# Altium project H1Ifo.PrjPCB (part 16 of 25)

## Sheet IfoSqz3B.SchDoc: D1800185
size C; Engineer: Daniel Sigg; DocumentNumber: 7; Revision: 4; SheetNumber: 7; SheetTotal: 10
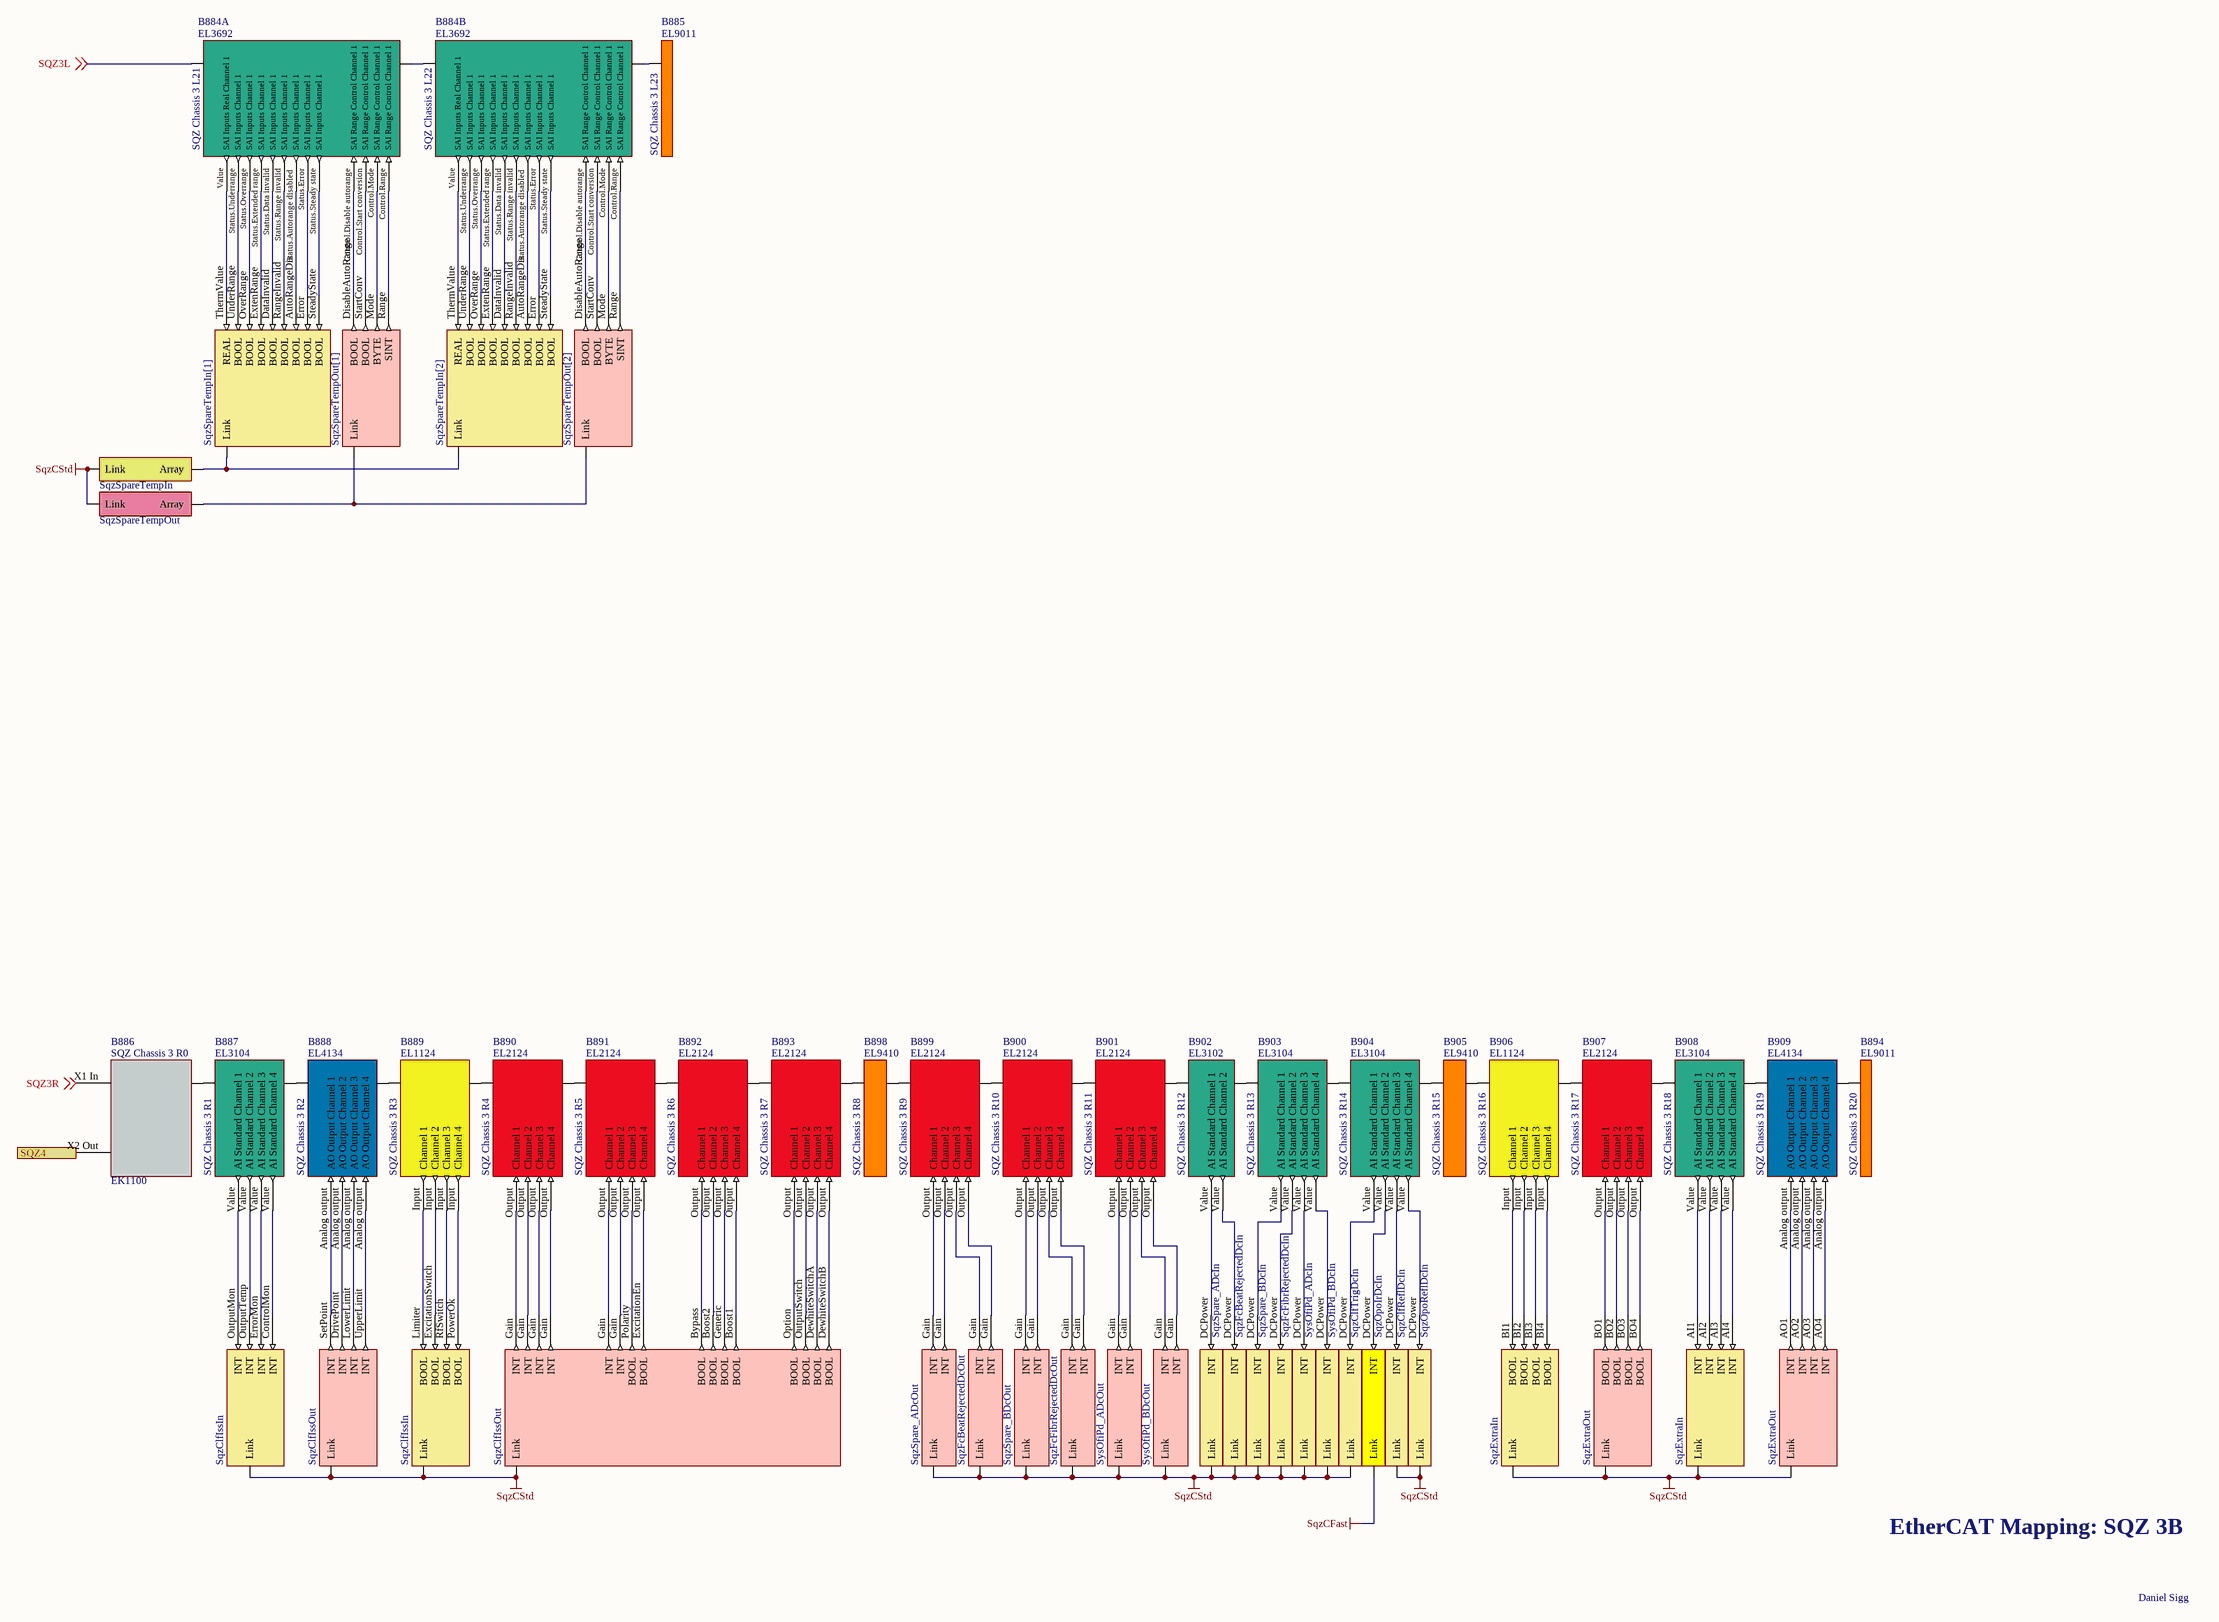
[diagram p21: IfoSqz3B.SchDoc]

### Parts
B884A  SQZ Chassis 3 L21  Part Number: EL3692  (mechanical)
B884B  SQZ Chassis 3 L22  Part Number: EL3692  (mechanical)
B885  SQZ Chassis 3 L23  Part Number: EL9011  (mechanical)
B886  SQZ Chassis 3 R0  Part Number: EK1100
B887  SQZ Chassis 3 R1  Part Number: EL3104  (mechanical)
B888  SQZ Chassis 3 R2  Part Number: EL4134  (mechanical)
B889  SQZ Chassis 3 R3  Part Number: EL1124  (mechanical)
B890  SQZ Chassis 3 R4  Part Number: EL2124  (mechanical)
B891  SQZ Chassis 3 R5  Part Number: EL2124  (mechanical)
B892  SQZ Chassis 3 R6  Part Number: EL2124  (mechanical)
B893  SQZ Chassis 3 R7  Part Number: EL2124  (mechanical)
B894  SQZ Chassis 3 R20  Part Number: EL9011  (mechanical)
B898  SQZ Chassis 3 R8  Part Number: EL9410  (mechanical)
B899  SQZ Chassis 3 R9  Part Number: EL2124  (mechanical)
B900  SQZ Chassis 3 R10  Part Number: EL2124  (mechanical)
B901  SQZ Chassis 3 R11  Part Number: EL2124  (mechanical)
B902  SQZ Chassis 3 R12  Part Number: EL3102  (mechanical)
B903  SQZ Chassis 3 R13  Part Number: EL3104  (mechanical)
B904  SQZ Chassis 3 R14  Part Number: EL3104  (mechanical)
B905  SQZ Chassis 3 R15  Part Number: EL9410  (mechanical)
B906  SQZ Chassis 3 R16  Part Number: EL1124  (mechanical)
B907  SQZ Chassis 3 R17  Part Number: EL2124  (mechanical)
B908  SQZ Chassis 3 R18  Part Number: EL3104  (mechanical)
B909  SQZ Chassis 3 R19  Part Number: EL4134  (mechanical)
V410  SqzClfIssIn  (parts A,B of 2)  (no BOM)
V411  SqzClfIssOut  (parts A,B of 2)  (no BOM)
V701  SqzSpareTempIn[1]  (no BOM)
V702  SqzSpareTempOut[1]  (no BOM)
V703  SqzSpareTempIn[2]  (no BOM)
V704  SqzSpareTempOut[2]  (no BOM)
V705  SqzSpareTempIn  (no BOM)
V706  SqzSpareTempOut  (no BOM)
V722  SqzSpare_ADcOut  (no BOM)
V723  SqzFcBeatRejectedDcOut  (no BOM)
V724  SqzFcFibrRejectedDcOut  (no BOM)
V725  SqzSpare_BDcOut  (no BOM)
V726  SysOfiPd_ADcOut  (no BOM)
V727  SysOfiPd_BDcOut  (no BOM)
V728  SqzSpare_ADcIn  (no BOM)
V729  SqzFcBeatRejectedDcIn  (no BOM)
V730  SqzFcFibrRejectedDcIn  (no BOM)
V731  SqzSpare_BDcIn  (no BOM)
V732  SysOfiPd_ADcIn  (no BOM)
V733  SysOfiPd_BDcIn  (no BOM)
V734  SqzClfTrigDcIn  (no BOM)
V735  SqzOpoIrDcIn  (no BOM)
V736  SqzClfReflDcIn  (no BOM)
V737  SqzOpoReflDcIn  (no BOM)
V738  SqzExtraIn  (parts A,B of 2)  (no BOM)
V739  SqzExtraOut  (parts A,B of 2)  (no BOM)

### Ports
SQZ4

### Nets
SqzCFast: V735.1(Link)
SqzCStd: V410.0(Link) V410.1(Link) V411.0(Link) V411.1(Link) V705.?1(Link) V706.?1(Link) V722.0(Link) V723.0(Link) V724.0(Link) V725.0(Link) V726.0(Link) V727.0(Link) V728.1(Link) V729.1(Link) V730.1(Link) V731.1(Link) V732.1(Link) V733.1(Link) V734.1(Link) V736.1(Link) V737.1(Link) V738.0(Link) V738.1(Link) V739.0(Link) V739.1(Link)
SQZ3L: B884A.Ebus(A) ; off-sheet SQZ3L
SQZ3R: B886.X1_In(A) ; off-sheet SQZ3R
NetB884A_Control.Disable autorange: B884A.Control.Disable_autorange(SAI_Range_Control_Channel_1) V702.DisableAutoRange(BOOL)
NetB884A_Control.Mode: B884A.Control.Mode(SAI_Range_Control_Channel_1) V702.Mode(BYTE)
NetB884A_Control.Range: B884A.Control.Range(SAI_Range_Control_Channel_1) V702.Range(SINT)
NetB884A_Control.Start conversion: B884A.Control.Start_conversion(SAI_Range_Control_Channel_1) V702.StartConv(BOOL)
NetB884A_Ebus: B884A.Ebus(B) B884B.Ebus(A)
NetB884A_Status.Autorange disabled: B884A.Status.Autorange_disabled(SAI_Inputs_Channel_1) V701.AutoRangeDis(BOOL)
NetB884A_Status.Data invalid: B884A.Status.Data_invalid(SAI_Inputs_Channel_1) V701.DataInvalid(BOOL)
NetB884A_Status.Error: B884A.Status.Error(SAI_Inputs_Channel_1) V701.Error(BOOL)
NetB884A_Status.Extended range: B884A.Status.Extended_range(SAI_Inputs_Channel_1) V701.ExtenRange(BOOL)
NetB884A_Status.Overrange: B884A.Status.Overrange(SAI_Inputs_Channel_1) V701.OverRange(BOOL)
NetB884A_Status.Range invalid: B884A.Status.Range_invalid(SAI_Inputs_Channel_1) V701.RangeInvalid(BOOL)
NetB884A_Status.Steady state: B884A.Status.Steady_state(SAI_Inputs_Channel_1) V701.SteadyState(BOOL)
NetB884A_Status.Underrange: B884A.Status.Underrange(SAI_Inputs_Channel_1) V701.UnderRange(BOOL)
NetB884A_Value: B884A.Value(SAI_Inputs_Real_Channel_1) V701.ThermValue(REAL)
NetB884B_Control.Disable autorange: B884B.Control.Disable_autorange(SAI_Range_Control_Channel_1) V704.DisableAutoRange(BOOL)
NetB884B_Control.Mode: B884B.Control.Mode(SAI_Range_Control_Channel_1) V704.Mode(BYTE)
NetB884B_Control.Range: B884B.Control.Range(SAI_Range_Control_Channel_1) V704.Range(SINT)
NetB884B_Control.Start conversion: B884B.Control.Start_conversion(SAI_Range_Control_Channel_1) V704.StartConv(BOOL)
NetB884B_Ebus: B884B.Ebus(B) B885.Ebus(A)
NetB884B_Status.Autorange disabled: B884B.Status.Autorange_disabled(SAI_Inputs_Channel_1) V703.AutoRangeDis(BOOL)
NetB884B_Status.Data invalid: B884B.Status.Data_invalid(SAI_Inputs_Channel_1) V703.DataInvalid(BOOL)
NetB884B_Status.Error: B884B.Status.Error(SAI_Inputs_Channel_1) V703.Error(BOOL)
NetB884B_Status.Extended range: B884B.Status.Extended_range(SAI_Inputs_Channel_1) V703.ExtenRange(BOOL)
NetB884B_Status.Overrange: B884B.Status.Overrange(SAI_Inputs_Channel_1) V703.OverRange(BOOL)
NetB884B_Status.Range invalid: B884B.Status.Range_invalid(SAI_Inputs_Channel_1) V703.RangeInvalid(BOOL)
NetB884B_Status.Steady state: B884B.Status.Steady_state(SAI_Inputs_Channel_1) V703.SteadyState(BOOL)
NetB884B_Status.Underrange: B884B.Status.Underrange(SAI_Inputs_Channel_1) V703.UnderRange(BOOL)
NetB884B_Value: B884B.Value(SAI_Inputs_Real_Channel_1) V703.ThermValue(REAL)
NetB886_Ebus: B886.Ebus(B) B887.Ebus(A)
NetB886_X2 Out: B886.X2_Out(C) ; port SQZ4
NetB887_Ebus: B887.Ebus(B) B888.Ebus(A)
NetB887_Value: B887.Value(AI_Standard_Channel_1) V410.OutputMon(INT)
NetB887_Value: B887.Value(AI_Standard_Channel_2) V410.OutputTemp(INT)  [a separate net that carries the same name]
NetB887_Value: B887.Value(AI_Standard_Channel_3) V410.ErrorMon(INT)  [a separate net that carries the same name]
NetB887_Value: B887.Value(AI_Standard_Channel_4) V410.ControlMon(INT)  [a separate net that carries the same name]
NetB888_Analog output: B888.Analog_output(AO_Output_Channel_1) V411.SetPoint(INT)
NetB888_Analog output: B888.Analog_output(AO_Output_Channel_2) V411.DrivePoint(INT)  [a separate net that carries the same name]
NetB888_Analog output: B888.Analog_output(AO_Output_Channel_3) V411.LowerLimit(INT)  [a separate net that carries the same name]
NetB888_Analog output: B888.Analog_output(AO_Output_Channel_4) V411.UpperLimit(INT)  [a separate net that carries the same name]
NetB888_Ebus: B888.Ebus(B) B889.Ebus(A)
NetB889_Ebus: B889.Ebus(B) B890.Ebus(A)
NetB889_Input: B889.Input(Channel_1) V410.Limiter(BOOL)
NetB889_Input: B889.Input(Channel_2) V410.ExcitationSwitch(BOOL)  [a separate net that carries the same name]
NetB889_Input: B889.Input(Channel_3) V410.RfSwitch(BOOL)  [a separate net that carries the same name]
NetB889_Input: B889.Input(Channel_4) V410.PowerOk(BOOL)  [a separate net that carries the same name]
NetB890_Ebus: B890.Ebus(B) B891.Ebus(A)
NetB890_Output: B890.Output(Channel_1) V411.Gain(INT)
NetB890_Output: B890.Output(Channel_2) V411.Gain(INT)  [a separate net that carries the same name]
NetB890_Output: B890.Output(Channel_3) V411.Gain(INT)  [a separate net that carries the same name]
NetB890_Output: B890.Output(Channel_4) V411.Gain(INT)  [a separate net that carries the same name]
NetB891_Ebus: B891.Ebus(B) B892.Ebus(A)
NetB891_Output: B891.Output(Channel_1) V411.Gain(INT)
NetB891_Output: B891.Output(Channel_2) V411.Gain(INT)  [a separate net that carries the same name]
NetB891_Output: B891.Output(Channel_3) V411.Polarity(BOOL)  [a separate net that carries the same name]
NetB891_Output: B891.Output(Channel_4) V411.ExcitationEn(BOOL)  [a separate net that carries the same name]
NetB892_Ebus: B892.Ebus(B) B893.Ebus(A)
NetB892_Output: B892.Output(Channel_1) V411.Bypass(BOOL)
NetB892_Output: B892.Output(Channel_2) V411.Boost2(BOOL)  [a separate net that carries the same name]
NetB892_Output: B892.Output(Channel_3) V411.Generic(BOOL)  [a separate net that carries the same name]
NetB892_Output: B892.Output(Channel_4) V411.Boost1(BOOL)  [a separate net that carries the same name]
NetB893_Ebus: B893.Ebus(B) B898.Ebus(A)
NetB893_Output: B893.Output(Channel_1) V411.Option(BOOL)
NetB893_Output: B893.Output(Channel_2) V411.OutputSwitch(BOOL)  [a separate net that carries the same name]
NetB893_Output: B893.Output(Channel_3) V411.DewhiteSwitchA(BOOL)  [a separate net that carries the same name]
NetB893_Output: B893.Output(Channel_4) V411.DewhiteSwitchB(BOOL)  [a separate net that carries the same name]
NetB894_Ebus: B894.Ebus(A) B909.Ebus(B)
NetB898_Ebus: B898.Ebus(B) B899.Ebus(A)
NetB899_Ebus: B899.Ebus(B) B900.Ebus(A)
NetB899_Output: B899.Output(Channel_1) V722.Gain(INT)
NetB899_Output: B899.Output(Channel_2) V722.Gain(INT)  [a separate net that carries the same name]
NetB899_Output: B899.Output(Channel_3) V723.Gain(INT)  [a separate net that carries the same name]
NetB899_Output: B899.Output(Channel_4) V723.Gain(INT)  [a separate net that carries the same name]
NetB900_Ebus: B900.Ebus(B) B901.Ebus(A)
NetB900_Output: B900.Output(Channel_1) V725.Gain(INT)
NetB900_Output: B900.Output(Channel_2) V725.Gain(INT)  [a separate net that carries the same name]
NetB900_Output: B900.Output(Channel_3) V724.Gain(INT)  [a separate net that carries the same name]
NetB900_Output: B900.Output(Channel_4) V724.Gain(INT)  [a separate net that carries the same name]
NetB901_Ebus: B901.Ebus(B) B902.Ebus(A)
NetB901_Output: B901.Output(Channel_1) V726.Gain(INT)
NetB901_Output: B901.Output(Channel_2) V726.Gain(INT)  [a separate net that carries the same name]
NetB901_Output: B901.Output(Channel_3) V727.Gain(INT)  [a separate net that carries the same name]
NetB901_Output: B901.Output(Channel_4) V727.Gain(INT)  [a separate net that carries the same name]
NetB902_Ebus: B902.Ebus(B) B903.Ebus(A)
NetB902_Value: B902.Value(AI_Standard_Channel_1) V728.DCPower(INT)
NetB902_Value: B902.Value(AI_Standard_Channel_2) V729.DCPower(INT)  [a separate net that carries the same name]
NetB903_Ebus: B903.Ebus(B) B904.Ebus(A)
NetB903_Value: B903.Value(AI_Standard_Channel_1) V731.DCPower(INT)
NetB903_Value: B903.Value(AI_Standard_Channel_2) V730.DCPower(INT)  [a separate net that carries the same name]
NetB903_Value: B903.Value(AI_Standard_Channel_3) V732.DCPower(INT)  [a separate net that carries the same name]
NetB903_Value: B903.Value(AI_Standard_Channel_4) V733.DCPower(INT)  [a separate net that carries the same name]
NetB904_Ebus: B904.Ebus(B) B905.Ebus(A)
NetB904_Value: B904.Value(AI_Standard_Channel_1) V734.DCPower(INT)
NetB904_Value: B904.Value(AI_Standard_Channel_2) V735.DCPower(INT)  [a separate net that carries the same name]
NetB904_Value: B904.Value(AI_Standard_Channel_3) V736.DCPower(INT)  [a separate net that carries the same name]
NetB904_Value: B904.Value(AI_Standard_Channel_4) V737.DCPower(INT)  [a separate net that carries the same name]
NetB905_Ebus: B905.Ebus(B) B906.Ebus(A)
NetB906_Ebus: B906.Ebus(B) B907.Ebus(A)
NetB906_Input: B906.Input(Channel_1) V738.BI1(BOOL)
NetB906_Input: B906.Input(Channel_2) V738.BI2(BOOL)  [a separate net that carries the same name]
NetB906_Input: B906.Input(Channel_3) V738.BI3(BOOL)  [a separate net that carries the same name]
NetB906_Input: B906.Input(Channel_4) V738.BI4(BOOL)  [a separate net that carries the same name]
NetB907_Ebus: B907.Ebus(B) B908.Ebus(A)
NetB907_Output: B907.Output(Channel_1) V739.BO1(BOOL)
NetB907_Output: B907.Output(Channel_2) V739.BO2(BOOL)  [a separate net that carries the same name]
NetB907_Output: B907.Output(Channel_3) V739.BO3(BOOL)  [a separate net that carries the same name]
NetB907_Output: B907.Output(Channel_4) V739.BO4(BOOL)  [a separate net that carries the same name]
NetB908_Ebus: B908.Ebus(B) B909.Ebus(A)
NetB908_Value: B908.Value(AI_Standard_Channel_1) V738.AI1(INT)
NetB908_Value: B908.Value(AI_Standard_Channel_2) V738.AI2(INT)  [a separate net that carries the same name]
NetB908_Value: B908.Value(AI_Standard_Channel_3) V738.AI3(INT)  [a separate net that carries the same name]
NetB908_Value: B908.Value(AI_Standard_Channel_4) V738.AI4(INT)  [a separate net that carries the same name]
NetB909_Analog output: B909.Analog_output(AO_Output_Channel_1) V739.AO1(INT)
NetB909_Analog output: B909.Analog_output(AO_Output_Channel_2) V739.AO2(INT)  [a separate net that carries the same name]
NetB909_Analog output: B909.Analog_output(AO_Output_Channel_3) V739.AO3(INT)  [a separate net that carries the same name]
NetB909_Analog output: B909.Analog_output(AO_Output_Channel_4) V739.AO4(INT)  [a separate net that carries the same name]
NetV701_1: V701.1(Link) V703.1(Link) V705.?2(Array)
NetV702_1: V702.1(Link) V704.1(Link) V706.?2(Array)

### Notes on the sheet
- EtherCAT Mapping: SQZ 3B
- Daniel Sigg

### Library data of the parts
B884A = TerminalEL3692-1chn: EtherCAT Terminal EL3692 1-chn Resistance Measurement; Rail: Left; BoxNextB: HCCQCWHL; BoxPrev: FHTRRYRM; PortPrevFull: 1141/B; PortPrevShort: B; Fullname: TIID^Vertex Squeezer (EtherCAT)^SQZ Chassis 3 L0 (EK1101)^SQZ Chassis 3 L21 (EL3692); BoxAddr: 1142; PDO Inputs: 0x1A00,0x1A02; PDO Outputs: 0x1600; Disabled: False
B884B = TerminalEL3692-1chn: EtherCAT Terminal EL3692 1-chn Resistance Measurement; Rail: Left; BoxNextB: CYSUGKJU; BoxPrev: BXXLOSJW; PortPrevFull: 1142/B; PortPrevShort: B; Fullname: TIID^Vertex Squeezer (EtherCAT)^SQZ Chassis 3 L0 (EK1101)^SQZ Chassis 3 L22 (EL3692); BoxAddr: 1143; PDO Inputs: 0x1A00,0x1A02; PDO Outputs: 0x1600; Disabled: False
B885 = TerminalEL9011: EtherCAT Terminal EL9011 End; BoxType: TerminalPassive; Rail: Left; BoxPrev: HCCQCWHL; PortPrevShort: B; Fullname: TIID^Vertex Squeezer (EtherCAT)^SQZ Chassis 3 L0 (EK1101)^SQZ Chassis 3 L23 (EL9011); Disabled: False
B886 = CouplerEK1100: EtherCAT Coupler; Rail: Right; BoxNextB: LMNHRKFK; BoxNextC: BCNOLNHC; BoxPrev: VQWTFMVH; PortPrevFull: 1144/C; PortPrevShort: C 'X2 Out'; Fullname: TIID^Vertex Squeezer (EtherCAT)^SQZ Chassis 3 R0 (EK1100); BoxPorts: Junction; BoxAddr: 1168; Disabled: False
B887 = TerminalEL3104: EtherCAT Terminal EL3104 4-chn Analog Input; Rail: Right; BoxNextB: SAJIWMHJ; BoxPrev: BKUDMEPV; PortPrevFull: 1168/B; PortPrevShort: B; Fullname: TIID^Vertex Squeezer (EtherCAT)^SQZ Chassis 3 R0 (EK1100)^SQZ Chassis 3 R1 (EL3104); BoxAddr: 1169; Disabled: False
B888 = TerminalEL4134: EtherCAT Terminal EL4134 4-chn Analog Ouput; Rail: Right; BoxNextB: JGBHBNGR; BoxPrev: LMNHRKFK; PortPrevFull: 1169/B; PortPrevShort: B; Fullname: TIID^Vertex Squeezer (EtherCAT)^SQZ Chassis 3 R0 (EK1100)^SQZ Chassis 3 R2 (EL4134); BoxAddr: 1170; Disabled: False
B889 = TerminalEL1124: EtherCAT Terminal EL1124 4-chn Digital Input; Rail: Right; BoxNextB: VKBNNKDD; BoxPrev: SAJIWMHJ; PortPrevFull: 1170/B; PortPrevShort: B; Fullname: TIID^Vertex Squeezer (EtherCAT)^SQZ Chassis 3 R0 (EK1100)^SQZ Chassis 3 R3 (EL1124); BoxAddr: 1171; Disabled: False
B890 = TerminalEL2124: EtherCAT Terminal EL2124 4-chn Digital Ouput; Rail: Right; BoxNextB: CQYTOJCV; BoxPrev: JGBHBNGR; PortPrevFull: 1171/B; PortPrevShort: B; Fullname: TIID^Vertex Squeezer (EtherCAT)^SQZ Chassis 3 R0 (EK1100)^SQZ Chassis 3 R4 (EL2124); BoxAddr: 1172; Disabled: False
B891 = TerminalEL2124: EtherCAT Terminal EL2124 4-chn Digital Ouput; Rail: Right; BoxNextB: GUINYQMW; BoxPrev: VKBNNKDD; PortPrevFull: 1172/B; PortPrevShort: B; Fullname: TIID^Vertex Squeezer (EtherCAT)^SQZ Chassis 3 R0 (EK1100)^SQZ Chassis 3 R5 (EL2124); BoxAddr: 1173; Disabled: False
B892 = TerminalEL2124: EtherCAT Terminal EL2124 4-chn Digital Ouput; Rail: Right; BoxNextB: HMWVQJTD; BoxPrev: CQYTOJCV; PortPrevFull: 1173/B; PortPrevShort: B; Fullname: TIID^Vertex Squeezer (EtherCAT)^SQZ Chassis 3 R0 (EK1100)^SQZ Chassis 3 R6 (EL2124); BoxAddr: 1174; Disabled: False
B893 = TerminalEL2124: EtherCAT Terminal EL2124 4-chn Digital Ouput; Rail: Right; BoxNextB: EWXBFFSC; BoxPrev: GUINYQMW; PortPrevFull: 1174/B; PortPrevShort: B; Fullname: TIID^Vertex Squeezer (EtherCAT)^SQZ Chassis 3 R0 (EK1100)^SQZ Chassis 3 R7 (EL2124); BoxAddr: 1175; Disabled: False
B894 = TerminalEL9011: EtherCAT Terminal EL9011 End; BoxType: TerminalPassive; Rail: Right; BoxPrev: REDTJCGQ; PortPrevShort: B; Fullname: TIID^Vertex Squeezer (EtherCAT)^SQZ Chassis 3 R0 (EK1100)^SQZ Chassis 3 R20 (EL9011); Disabled: False
B898 = TerminalEL9410: EtherCAT Terminal EL9410 Power; Rail: Right; BoxNextB: TDWNLRLC; BoxPrev: HMWVQJTD; PortPrevFull: 1175/B; PortPrevShort: B; Fullname: TIID^Vertex Squeezer (EtherCAT)^SQZ Chassis 3 R0 (EK1100)^SQZ Chassis 3 R8 (EL9410); BoxAddr: 1176; Disabled: False
B899 = TerminalEL2124: EtherCAT Terminal EL2124 4-chn Digital Ouput; Rail: Right; BoxNextB: JKJTFGCV; BoxPrev: EWXBFFSC; PortPrevFull: 1176/B; PortPrevShort: B; Fullname: TIID^Vertex Squeezer (EtherCAT)^SQZ Chassis 3 R0 (EK1100)^SQZ Chassis 3 R9 (EL2124); BoxAddr: 1177; Disabled: False
B900 = TerminalEL2124: EtherCAT Terminal EL2124 4-chn Digital Ouput; Rail: Right; BoxNextB: YYBAPAKS; BoxPrev: TDWNLRLC; PortPrevFull: 1177/B; PortPrevShort: B; Fullname: TIID^Vertex Squeezer (EtherCAT)^SQZ Chassis 3 R0 (EK1100)^SQZ Chassis 3 R10 (EL2124); BoxAddr: 1178; Disabled: False
B901 = TerminalEL2124: EtherCAT Terminal EL2124 4-chn Digital Ouput; Rail: Right; BoxNextB: KULEGXXY; BoxPrev: JKJTFGCV; PortPrevFull: 1178/B; PortPrevShort: B; Fullname: TIID^Vertex Squeezer (EtherCAT)^SQZ Chassis 3 R0 (EK1100)^SQZ Chassis 3 R11 (EL2124); BoxAddr: 1179; Disabled: False
B902 = TerminalEL3102: EtherCAT Terminal EL3102 2-chn Analog Input; Rail: Right; BoxNextB: QOIJDIEC; BoxPrev: YYBAPAKS; PortPrevFull: 1179/B; PortPrevShort: B; Fullname: TIID^Vertex Squeezer (EtherCAT)^SQZ Chassis 3 R0 (EK1100)^SQZ Chassis 3 R12 (EL3102); BoxAddr: 1180; Disabled: False
B903 = TerminalEL3104: EtherCAT Terminal EL3104 4-chn Analog Input; Rail: Right; BoxNextB: XSWHLOWF; BoxPrev: KULEGXXY; PortPrevFull: 1180/B; PortPrevShort: B; Fullname: TIID^Vertex Squeezer (EtherCAT)^SQZ Chassis 3 R0 (EK1100)^SQZ Chassis 3 R13 (EL3104); BoxAddr: 1181; Disabled: False
B904 = TerminalEL3104: EtherCAT Terminal EL3104 4-chn Analog Input; Rail: Right; BoxNextB: DXXDEXAW; BoxPrev: QOIJDIEC; PortPrevFull: 1181/B; PortPrevShort: B; Fullname: TIID^Vertex Squeezer (EtherCAT)^SQZ Chassis 3 R0 (EK1100)^SQZ Chassis 3 R14 (EL3104); BoxAddr: 1182; Disabled: False
B905 = TerminalEL9410: EtherCAT Terminal EL9410 Power; Rail: Right; BoxNextB: LQYWWYRA; BoxPrev: XSWHLOWF; PortPrevFull: 1182/B; PortPrevShort: B; Fullname: TIID^Vertex Squeezer (EtherCAT)^SQZ Chassis 3 R0 (EK1100)^SQZ Chassis 3 R15 (EL9410); BoxAddr: 1183; Disabled: False
B906 = TerminalEL1124: EtherCAT Terminal EL1124 4-chn Digital Input; Rail: Right; BoxNextB: KAAFGPDB; BoxPrev: DXXDEXAW; PortPrevFull: 1183/B; PortPrevShort: B; Fullname: TIID^Vertex Squeezer (EtherCAT)^SQZ Chassis 3 R0 (EK1100)^SQZ Chassis 3 R16 (EL1124); BoxAddr: 1184; Disabled: False
B907 = TerminalEL2124: EtherCAT Terminal EL2124 4-chn Digital Ouput; Rail: Right; BoxNextB: YRGWWXTI; BoxPrev: LQYWWYRA; PortPrevFull: 1184/B; PortPrevShort: B; Fullname: TIID^Vertex Squeezer (EtherCAT)^SQZ Chassis 3 R0 (EK1100)^SQZ Chassis 3 R17 (EL2124); BoxAddr: 1185; Disabled: False
B908 = TerminalEL3104: EtherCAT Terminal EL3104 4-chn Analog Input; Rail: Right; BoxNextB: REDTJCGQ; BoxPrev: KAAFGPDB; PortPrevFull: 1185/B; PortPrevShort: B; Fullname: TIID^Vertex Squeezer (EtherCAT)^SQZ Chassis 3 R0 (EK1100)^SQZ Chassis 3 R18 (EL3104); BoxAddr: 1186; Disabled: False
B909 = TerminalEL4134: EtherCAT Terminal EL4134 4-chn Analog Ouput; Rail: Right; BoxNextB: RXFIDCPJ; BoxPrev: YRGWWXTI; PortPrevFull: 1186/B; PortPrevShort: B; Fullname: TIID^Vertex Squeezer (EtherCAT)^SQZ Chassis 3 R0 (EK1100)^SQZ Chassis 3 R19 (EL4134); BoxAddr: 1187; Disabled: False
V410 = Iss_AomServoInStruct: AomServoInStruct; BoxType: Variable; Instance: H1SqzCorner Instance; PLC: H1SqzCorner; Task: SqzCStd
V411 = Iss_AomServoOutStruct: AomServoOutStruct; BoxType: Variable; Instance: H1SqzCorner Instance; PLC: H1SqzCorner; Task: SqzCStd
V701 V703 = TECController_ThermistorInStruct: ThermistorInStruct; BoxType: Variable; Instance: H1SqzCorner Instance; PLC: H1SqzCorner; Task: SqzCStd
V702 V704 = TECController_ThermistorOutStruct: ThermistorOutStruct; BoxType: Variable; Instance: H1SqzCorner Instance; PLC: H1SqzCorner; Task: SqzCStd
V705 = ArrayAggregatorIn: Array [1..2] Of ThermistorInStruct; Instance: H1SqzCorner Instance; PLC: H1SqzCorner; Task: SqzCStd; Lower Bound: 1; Upper Bound: 2
V706 = ArrayAggregatorOut: Array [1..2] Of ThermistorOutStruct; Instance: H1SqzCorner Instance; PLC: H1SqzCorner; Task: SqzCStd; Lower Bound: 1; Upper Bound: 2
V722-V727 = DCPower_DCPowerOutStruct: DCPowerOutStruct; BoxType: Variable; Instance: H1SqzCorner Instance; PLC: H1SqzCorner; Task: SqzCStd
V728-V734 V736 V737 = DCPower_DCPowerInStruct: DCPowerInStruct; BoxType: Variable; Instance: H1SqzCorner Instance; PLC: H1SqzCorner; Task: SqzCStd
V735 = DCPower_DCPowerFastInStruct: DCPowerInStruct; BoxType: Variable; Instance: H1SqzCorner Instance; PLC: H1SqzCorner; Task: SqzCFast
V738 = Auxiliary_AuxiliaryInStruct: AuxiliaryInStruct; BoxType: Variable; Instance: H1SqzCorner Instance; PLC: H1SqzCorner; Task: SqzCStd
V739 = Auxiliary_AuxiliaryOutStruct: AuxiliaryOutStruct; BoxType: Variable; Instance: H1SqzCorner Instance; PLC: H1SqzCorner; Task: SqzCStd

## Sheet IfoEndX0.SchDoc: D1800185
size C; Engineer: Daniel Sigg; DocumentNumber: 4; Revision: 4; SheetNumber: 4; SheetTotal: 8
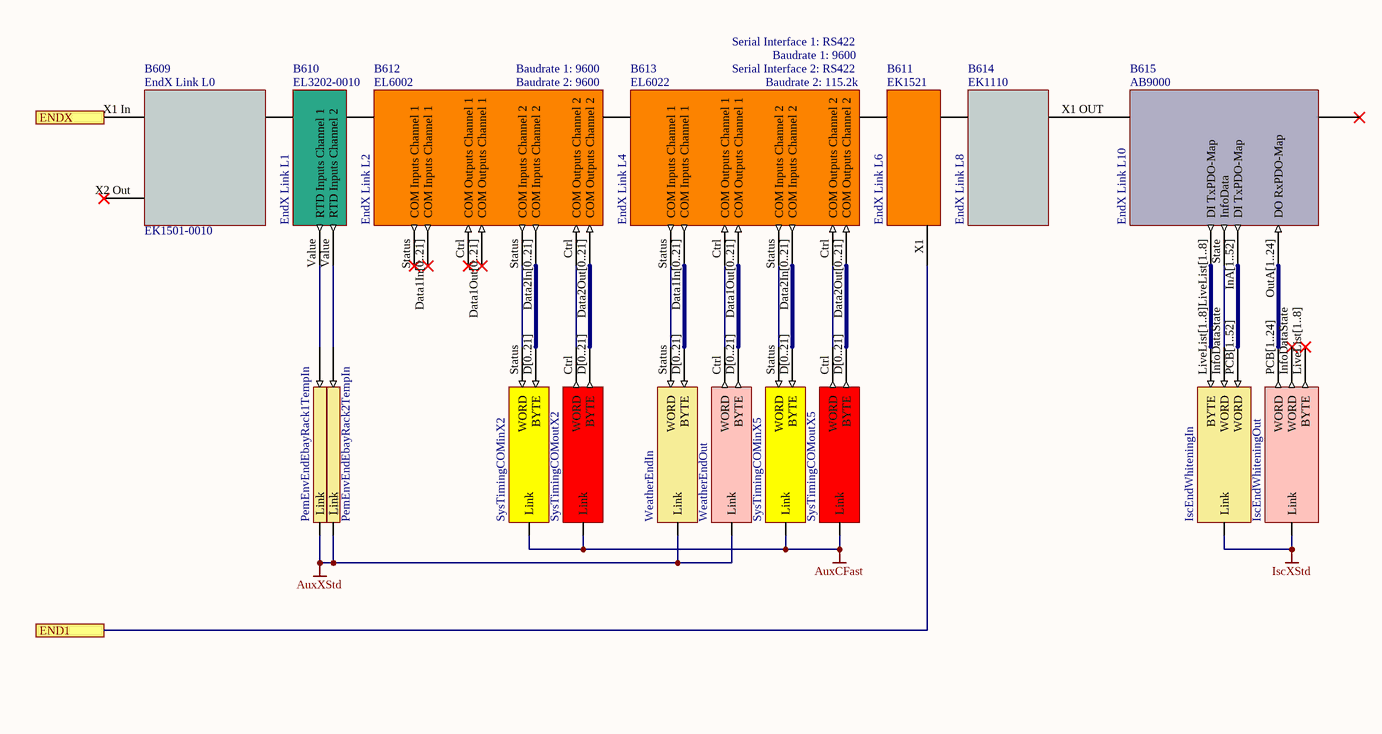
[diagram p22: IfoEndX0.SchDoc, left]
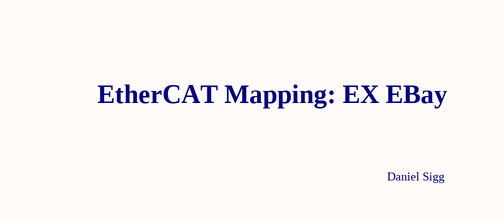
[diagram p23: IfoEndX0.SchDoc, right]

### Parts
B609  EndX Link L0  Part Number: EK1501-0010  (mechanical)
B610  EndX Link L1  Part Number: EL3202-0010  (mechanical)
B611  EndX Link L6  Part Number: EK1521  (mechanical)
B612  EndX Link L2  Part Number: EL6002  Baudrate 1: 9600  (mechanical)
B613  EndX Link L4  Part Number: EL6022  Baudrate 1: 9600  Baudrate 2: 115.2k  Serial Interface 1: RS422  (mechanical)
B614  EndX Link L8  Part Number: EK1110  (mechanical)
B615  EndX Link L10  Part Number: AB9000  (mechanical)
V526  PemEnvEndEbayRack1TempIn  (no BOM)
V527  PemEnvEndEbayRack2TempIn  (no BOM)
V528  IscEndWhiteningIn  (no BOM)
V529  IscEndWhiteningOut  (no BOM)
V530  SysTimingCOMinX2  (no BOM)
V531  SysTimingCOMoutX2  (no BOM)
V533  SysTimingCOMinX5  (no BOM)
V534  SysTimingCOMoutX5  (no BOM)
V845  WeatherEndIn  (no BOM)
V846  WeatherEndOut  (no BOM)

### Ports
END1, ENDX

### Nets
AuxCFast: V530.?1(Link) V531.?1(Link) V533.?1(Link) V534.?1(Link)
AuxXStd: V526.?2(Link) V527.?2(Link) V845.?1(Link) V846.?1(Link)
IscXStd: V528.?1(Link) V529.?1(Link)
NetB609_Ebus: B609.Ebus(B) B610.Ebus(A)
NetB609_X1 In: B609.X1_In(A) ; port ENDX
NetB610_Ebus: B610.Ebus(B) B612.Ebus(A)
NetB610_Value: B610.Value(RTD_Inputs_Channel_1) V526.?1
NetB610_Value: B610.Value(RTD_Inputs_Channel_2) V527.?1  [a separate net that carries the same name]
NetB611_Ebus: B611.Ebus(A) B613.Ebus(B)
NetB611_Ebus: B611.Ebus(C) B614.Ebus(A)  [a separate net that carries the same name]
NetB611_X1: B611.X1(D) ; port END1
NetB612_Ctrl: B612.Ctrl(COM_Outputs_Channel_1) V531.Ctrl(WORD)
NetB612_Data2In[0..21]: B612.Data2In[0..21](COM_Inputs_Channel_2) V530.D[0..21](BYTE)
NetB612_Data2Out[0..21]: B612.Data2Out[0..21](COM_Outputs_Channel_2) V531.D[0..21](BYTE)
NetB612_Ebus: B612.Ebus(B) B613.Ebus(A)
NetB612_Status: B612.Status(COM_Inputs_Channel_1) V530.Status(WORD)
NetB613_Ctrl: B613.Ctrl(COM_Outputs_Channel_1) V846.Ctrl(WORD)
NetB613_Ctrl: B613.Ctrl(COM_Outputs_Channel_2) V534.Ctrl(WORD)  [a separate net that carries the same name]
NetB613_Data1In[0..21]: B613.Data1In[0..21](COM_Inputs_Channel_1) V845.D[0..21](BYTE)
NetB613_Data1Out[0..21]: B613.Data1Out[0..21](COM_Outputs_Channel_1) V846.D[0..21](BYTE)
NetB613_Data2In[0..21]: B613.Data2In[0..21](COM_Inputs_Channel_2) V533.D[0..21](BYTE)
NetB613_Data2Out[0..21]: B613.Data2Out[0..21](COM_Outputs_Channel_2) V534.D[0..21](BYTE)
NetB613_Status: B613.Status(COM_Inputs_Channel_1) V845.Status(WORD)
NetB613_Status: B613.Status(COM_Inputs_Channel_2) V533.Status(WORD)  [a separate net that carries the same name]
NetB614_X1 OUT: B614.X1_OUT(B) B615.?2(A)
NetB615_InA[1..52]: B615.InA[1..52](DI_TxPDO-Map) V528.PCB[1..52](WORD)
NetB615_LiveList[1..8]: B615.LiveList[1..8](DI_TxPDO-Map) V528.LiveList[1..8](BYTE)
NetB615_OutA[1..24]: B615.OutA[1..24](DO_RxPDO-Map) V529.PCB[1..24](WORD)
NetB615_State: B615.State(InfoData) V528.InfoDataState(WORD)

Not connected (* = marked no-connect by the designer): B609 X2 Out(C)*; B612 Data1In[0..21](COM_Inputs_Channel_1)* Data1Out[0..21](COM_Outputs_Channel_1)*; B615 ?1(B)*; V529 InfoDataState(WORD)* LiveList[1..8](BYTE)*

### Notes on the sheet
- EtherCAT Mapping: EX EBay
- Daniel Sigg

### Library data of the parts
B609 = CouplerEK1501: Fiber Coupler; Rail: Left; BoxNextB: UNLNFJLN; BoxPrev: CLSUUFOZ; PortPrevFull: 1001/B; PortPrevShort: B 'X1'; Fullname: TIID^End X (EtherCAT)^EndX Link L0 (EK1501-0010); BoxPorts: Junction; BoxAddr: 1002; Disabled: False
B610 = TerminalEL3202-0010: EtherCAT Terminal EL3202-0010 2-chn Temperature Input; Rail: Left; BoxNextB: FGQAFBHR; BoxPrev: PMEMEWCT; PortPrevFull: 1002/B; PortPrevShort: B; Fullname: TIID^End X (EtherCAT)^EndX Link L0 (EK1501-0010)^EndX Link L1 (EL3202-0010); BoxAddr: 1003; Disabled: False
B611 = TerminalEK1521: EtherCAT Terminal Fiber; Rail: Left; BoxNextC: IBXWRMDF; BoxNextD: QEYXEFKI; BoxPrev: BNXINGGL; PortPrevFull: 1005/B; PortPrevShort: B; Fullname: TIID^End X (EtherCAT)^EndX Link L0 (EK1501-0010)^EndX Link L6 (EK1521); BoxPorts: Junction; BoxAddr: 1006; Disabled: False
B612 = TerminalEL6002: EtherCAT Terminal EL6002 Dual RS232; Rail: Left; BoxNextB: BNXINGGL; BoxPrev: UNLNFJLN; PortPrevFull: 1003/B; PortPrevShort: B; Fullname: TIID^End X (EtherCAT)^EndX Link L0 (EK1501-0010)^EndX Link L2 (EL6002); BoxAddr: 1004; BoxSubType: 9101; Disabled: False
B613 = TerminalEL6022: EtherCAT Terminal EL6022 Dual RS422; Rail: Left; BoxNextB: QCEWWLIP; BoxPrev: FGQAFBHR; PortPrevFull: 1004/B; PortPrevShort: B; Fullname: TIID^End X (EtherCAT)^EndX Link L0 (EK1501-0010)^EndX Link L4 (EL6022); BoxAddr: 1005; BoxSubType: 9103; Disabled: False
B614 = CouplerEK1110: EtherCAT Coupler Extension; BoxType: Terminal; Rail: Left; BoxNextB: PSHPKMCT; BoxPrev: QCEWWLIP; PortPrevFull: 1006/C; PortPrevShort: C; Fullname: TIID^End X (EtherCAT)^EndX Link L0 (EK1501-0010)^EndX Link L8 (EK1110); BoxAddr: 1126; Disabled: False
B615 = Anybus X-gateway 1xBIO: EtherCAT Modbus gateway for 1xBIO; Part Revision: V0000001b_P0000001b_R0001000d; BoxType: Box; BoxPrev: IBXWRMDF; PortPrevFull: 1126/B; PortPrevShort: B 'X1 OUT'; Fullname: TIID^End X (EtherCAT)^EndX Link L10 (AB9000); BoxAddr: 1127; PDO Inputs: 0x1A01; PDO Outputs: 0x1601; Disabled: False
V526 V527 = VariableInINT: INT; PLC: H1AuxEndX; Task: AuxEStd; Instance: H1AuxEndX Instance
V528 = ISCWhitening_IscWhiteningInStruct: IscWhiteningInStruct; BoxType: Variable; Instance: H1IscEndX Instance; PLC: H1IscEndX; Task: IscEStd
V529 = ISCWhitening_IscWhiteningOutStruct: IscWhiteningOutStruct; BoxType: Variable; Instance: H1IscEndX Instance; PLC: H1IscEndX; Task: IscEStd
V530 V533 = Serial_EL6inData22Bfast: EL6inData22B; PLC: H1AuxCorner; Task: AuxCFast; BoxType: Variable; Instance: H1AuxCorner Instance
V531 V534 = Serial_EL6outData22Bfast: EL6outData22B; PLC: H1AuxCorner; Task: AuxCFast; BoxType: Variable; Instance: H1AuxCorner Instance
V845 = Serial_EL6inData22B: EL6inData22B; PLC: H1AuxEndX; Task: AuxEStd; BoxType: Variable; Instance: H1AuxEndX Instance
V846 = Serial_EL6outData22B: EL6outData22B; PLC: H1AuxEndX; Task: AuxEStd; BoxType: Variable; Instance: H1AuxEndX Instance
